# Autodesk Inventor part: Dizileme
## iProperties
Company: Autodesk, Inc.
Shininess: 64.0
Length Units: 11269
Angle Units: 11279
Time Units: 11290
Mass Units: 11283
Length Display Precision: 3
Angle Display Precision: 2
Compacted: True
Part Number: Dizileme
Document SubType Name: Modeling
Created: 2003-12
Catalog Web Link: www.autodesk.com
Vendor: Autodesk, Inc.
Designer: Administrator
Manufacturer: Standard
Standards Organization: Custom
Density: 1 g/cm^3
Density: 0.0
Volumn: 0.0
Area: 0.0
PropertySet Name: Model Information
Control State: 0
Master: False
Checked Out: False
Author: Administrator
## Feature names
1. Extrusion1
2. Extrusion2
3. FaceDraft1
4. Fillet1
5. Fillet3
6. Shell1
7. Extrusion3
8. Hole1
9. Hole2
10. Extrusion4
11. Extrusion5
12. Extrusion6
13. Hole3
